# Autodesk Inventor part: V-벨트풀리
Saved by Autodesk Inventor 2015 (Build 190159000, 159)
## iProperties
Created: 2025-08
Part Number: V-벨트풀리
Material: 일반
Document SubType Name: Modeling
Designer: user
Density: 1 g/cm^3
Appearance: 기본값
Author: jhkim
Creation Date: 2025-08-05
Sending System: Autodesk Inventor 2026
Preprocessor: ST-DEVELOPER v20.1
Author: user
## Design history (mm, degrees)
node "V-벨트풀리1"
node "솔리드1"
node "기준1"
